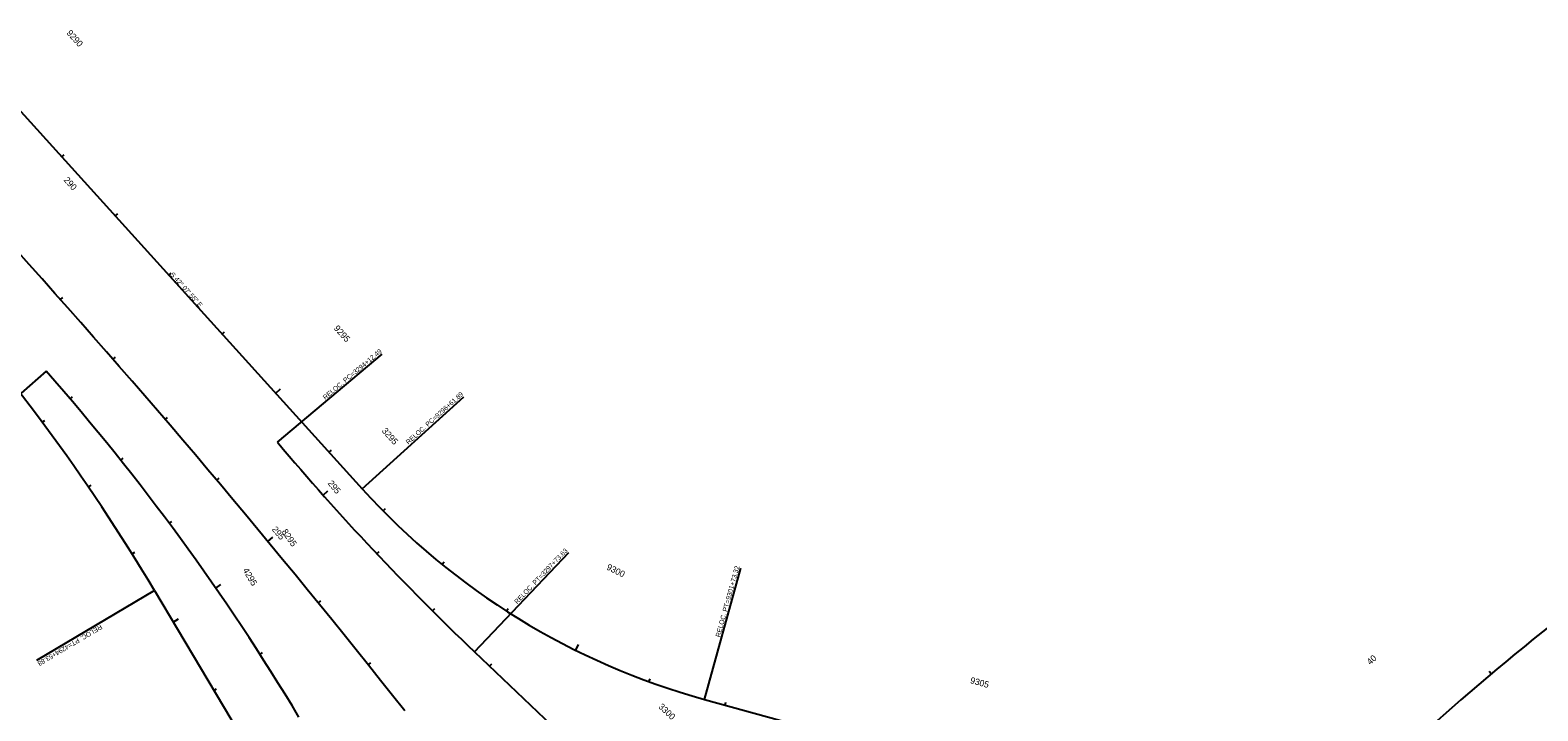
# Model space of a CAD drawing. Extents: x 1944333 to 1978554, y 788952 to 827675.
# Drawn here: x 1963366 to 1965258, y 805077 to 805932 of the extents above; entities that cross this region are included whole.
import ezdxf

# ---------------------------------------------------------------- set-up
doc = ezdxf.new("R2010")
doc.units = 0
for name, color, linetype in [('RD_HC_CL_Rel', 7, 'Continuous'), ('RD_HC_Data_Rel', 7, 'Continuous'), ('RD_HC_Data_Tic_Rel', 7, 'Continuous'), ('RD_HC_TX_Rel_Sta50', 7, 'Continuous')]:
    doc.layers.add(name, color=color, linetype=linetype)

msp = doc.modelspace()

# ---------------------------------------------------------------- linework, layer by layer
at = {"layer": 'RD_HC_CL_Rel'}
for p, q in [((1963334.8, 805851.3), (1963783, 805355.8)), ((1963522.1, 805228.1), (1963801.8, 804757.9)), ((1963923.8, 805151.2), (1964383.9, 804713.4)), ((1964212.7, 805091.2), (1964673.5, 804964.5))]:
    msp.add_line(p, q, dxfattribs=at)
for centre, radius, start, end in [((1954834, 797986.6), 11459.2, 38.22442, 42.13195), ((1961373.6, 803949.9), 2500, 30.7484, 42.1319), ((1961141.9, 803530.9), 2988, 30.9813, 41.3136), ((1966152.9, 807494.2), 3234, 220.0296, 226.4277), ((1964451.9, 805960.9), 902, 222.1319, 254.6189), ((1967047.5, 802933.9), 2864.9, 122.5648, 132.0581)]:
    msp.add_arc(centre, radius, start, end, dxfattribs=at)
at = {"layer": 'RD_HC_Data_Rel'}
for p, q in [((1963676.6, 805414.2), (1963808.1, 805524.7)), ((1963386.3, 805503.5), (1963257.2, 805390.1)), ((1963783, 805355.8), (1963910.4, 805471.1)), ((1963923.8, 805151.2), (1964042.4, 805275.8)), ((1964212.7, 805091.2), (1964258, 805256.2)), ((1963522.1, 805228.1), (1963374.2, 805140.1))]:
    msp.add_line(p, q, dxfattribs=at)
at = {"layer": 'RD_HC_Data_Tic_Rel'}
for p, q in [((1963406.1, 805772.5), (1963409, 805775.2)), ((1963473.1, 805698.4), (1963476.1, 805701.1)), ((1963540.2, 805624.2), (1963543.2, 805626.9)), ((1963404.2, 805593.4), (1963407.2, 805596.1)), ((1963607.3, 805550.1), (1963610.3, 805552.7)), ((1963470.3, 805518.4), (1963473.3, 805521)), ((1963416.4, 805468.7), (1963419.4, 805471.3)), ((1963674.4, 805475.9), (1963680.3, 805481.3)), ((1963381.5, 805439.3), (1963384.7, 805441.7)), ((1963535.7, 805442.7), (1963538.7, 805445.3)), ((1963741.5, 805401.7), (1963744.4, 805404.4)), ((1963479.9, 805391.5), (1963483.1, 805394)), ((1963439.4, 805357.8), (1963442.7, 805360.1)), ((1963600.4, 805366.5), (1963603.5, 805369.1)), ((1963733.8, 805347.9), (1963739.8, 805353.2)), ((1963809.1, 805328.1), (1963812, 805330.9)), ((1963540.9, 805312.2), (1963544.1, 805314.6)), ((1963664.5, 805289.7), (1963670.6, 805294.8)), ((1963494.1, 805274.1), (1963497.5, 805276.2)), ((1963801.3, 805274.2), (1963804.2, 805276.9)), ((1963883.1, 805260.9), (1963885.6, 805264)), ((1963599.1, 805231), (1963605.7, 805235.5)), ((1963727.9, 805212.4), (1963731, 805214.9)), ((1963545.7, 805188.4), (1963552.6, 805192.5)), ((1963871, 805202.5), (1963873.9, 805205.4)), ((1963964, 805202.3), (1963966.2, 805205.6)), ((1963654.7, 805147.8), (1963658, 805150)), ((1964051, 805152.9), (1964054.5, 805160.1)), ((1963790.6, 805134.5), (1963793.7, 805137)), ((1963942.9, 805133), (1963945.7, 805135.9)), ((1964142.8, 805113.5), (1964144.2, 805117.3)), ((1965199.8, 805123.4), (1965197.3, 805126.5)), ((1963596.8, 805102.5), (1963600.3, 805104.5)), ((1964238.4, 805084.2), (1964239.4, 805088))]:
    msp.add_line(p, q, dxfattribs=at)

# ---------------------------------------------------------------- texts
at = {"layer": 'RD_HC_Data_Rel'}
for s, rotation, p in [('S 42%%d 07\' 55" E', 312.1319, (1963541.4, 805624.4)), ('RELOC. PC=3294+12.49', 40.0296, (1963736.6, 805467.2)), ('RELOC. PC=9296+61.89', 42.1319, (1963841, 805411)), ('RELOC. PT=3297+73.63', 46.4277, (1963977.5, 805210.5)), ('RELOC. PT=9301+73.32', 74.6189, (1964232, 805168.9)), ('RELOC. PT=4294+53.88', 210.7484, (1963454.4, 805185.5))]:
    msp.add_text(s, height=6, rotation=rotation, dxfattribs=at).set_placement(p)
at = {"layer": 'RD_HC_TX_Rel_Sta50'}
for s, rotation, p in [('9290', 312.1319, (1963411.4, 805927.6)), ('290', 312.092, (1963407.8, 805743)), ('9295', 312.1319, (1963746.8, 805556.8)), ('3295', 311.58, (1963807, 805428.1)), ('295', 309.592, (1963739.2, 805362.3)), ('295', 309.592, (1963669.1, 805304.5)), ('8295', 304.6786, (1963681.5, 805301.8)), ('4295', 300.7484, (1963632.7, 805253.4)), ('9300', 333.6092, (1964088.8, 805254.8)), ('40', 42.0581, (1965048, 805134)), ('9305', 344.6189, (1964545.3, 805111.8)), ('3300', 316.4277, (1964154, 805081.3))]:
    msp.add_text(s, height=8, rotation=rotation, dxfattribs=at).set_placement(p)

doc.saveas('drawing.dxf')
